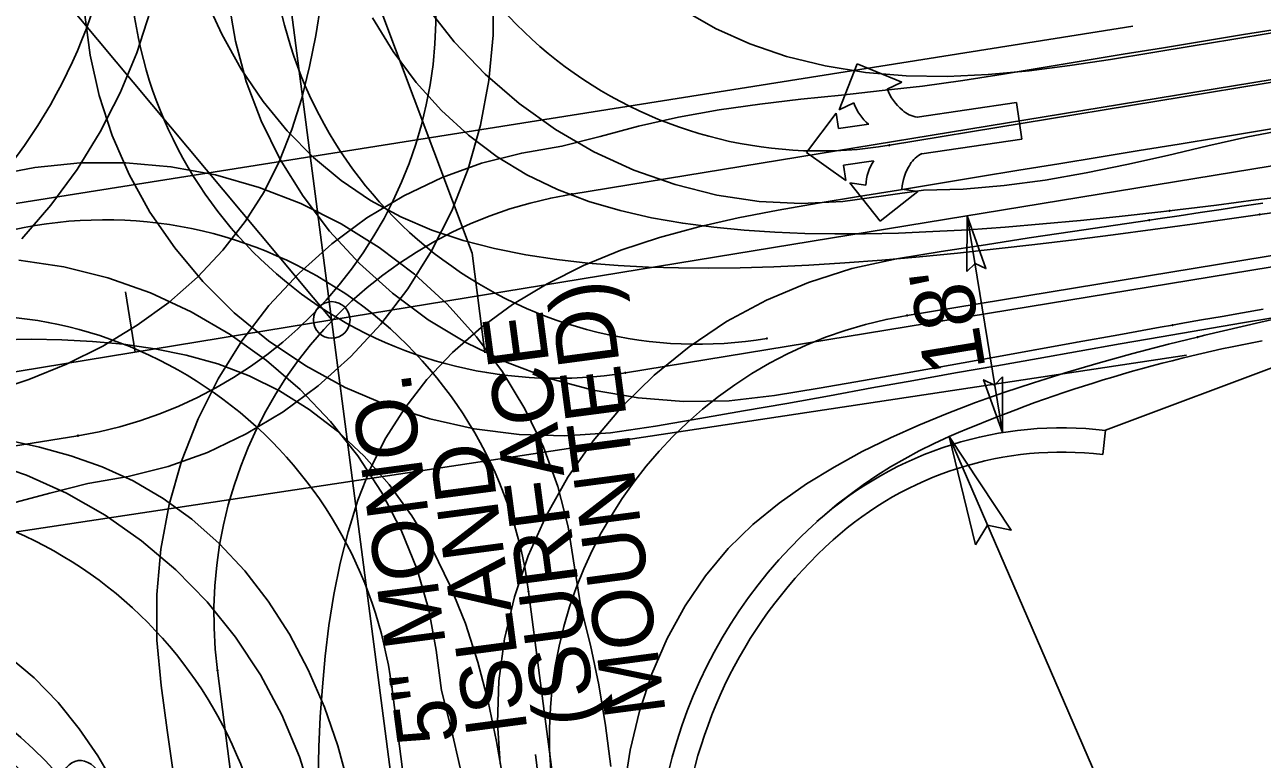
# Model space of a CAD drawing. Extents: x 2367848 to 2369479, y 800728 to 808616.
# Drawn here: x 2368356.4 to 2368457.9, y 807914.7 to 807974.9 of the extents above; entities that cross this region are included whole.
import ezdxf

# ---------------------------------------------------------------- set-up
doc = ezdxf.new("R2010")
doc.units = 0
for name, color, linetype in [('Default', 7, 'Continuous'), ('Prop AutoTurn Projected Path', 7, 'Continuous'), ('Prop AutoTurn Simulation', 7, 'Continuous'), ('Prop Conc 2ft 6in Curb and Gutter', 7, 'Continuous'), ('Prop Dimension', 7, 'Continuous'), ('Prop EOT', 7, 'Continuous'), ('Prop Horizontal Alignment', 7, 'Continuous'), ('Prop Horizontal Alignment Station Label', 7, 'Continuous'), ('Prop Horizontal Alignment Tick Small', 7, 'Continuous'), ('Prop Lane Arrow CELL', 7, 'Continuous'), ('Prop Paved Shoulder', 7, 'Continuous'), ('Prop Terminator CELL', 7, 'Continuous'), ('Prop WCC CELL', 7, 'Continuous'), ('Prop WCR CELL', 7, 'Continuous'), ('Scratch_Level_0', 7, 'Continuous'), ('Scratch_Level_1', 7, 'Continuous')]:
    doc.layers.add(name, color=color, linetype=linetype)

# ---------------------------------------------------------------- blocks, each defined once
blk = doc.blocks.new('CR')
at = {"layer": 'Prop WCC CELL'}
blk.add_ellipse((0.02, -0.02), major_axis=(5.61, 0), ratio=0.462467, dxfattribs=at)
blk.add_text('CR', height=3, dxfattribs=at).set_placement((-2.34, -1.5))

msp = doc.modelspace()

# ---------------------------------------------------------------- linework, layer by layer
at = {"layer": 'Default'}
for p, q in [((2368447.26, 807974.78), (2368313.92, 807953.63)), ((2368318.18, 807927.65), (2368451.68, 807947.82))]:
    msp.add_line(p, q, dxfattribs=at)
at = {"layer": 'Prop AutoTurn Projected Path'}
for p, q in [((2368427.31, 807965.02), (2368461.82, 807970.7)), ((2368428.77, 807951.07), (2368518.53, 807965.84)), ((2368402.03, 807801.48), (2368386.52, 807920.63))]:
    msp.add_line(p, q, dxfattribs=at)
for centre, radius, start, end in [((2368322.12, 807989.26), 42, 279.3467, 7.418), ((2368421.62, 807999.55), 35, 187.418, 279.3467), ((2368421.62, 807999.55), 35, 187.418, 279.3467), ((2368411.59, 807983.71), 35, 187.418, 279.3467), ((2368351.81, 807916.11), 35, 7.418, 99.3467), ((2368434.45, 807916.53), 35, 99.3467, 187.418), ((2368341.65, 807901.26), 35, 7.418, 99.3467)]:
    msp.add_arc(centre, radius, start, end, dxfattribs=at)
at = {"layer": 'Prop AutoTurn Simulation'}
for points in [[(2368373.15, 807976.86), (2368373.7, 807973.55), (2368374.59, 807970.25), (2368375.82, 807967.01), (2368377.38, 807963.86), (2368379.25, 807960.84), (2368381.42, 807957.99), (2368383.87, 807955.33), (2368386.58, 807952.9), (2368389.51, 807950.72), (2368392.66, 807948.81), (2368395.98, 807947.2), (2368399.45, 807945.9), (2368403.03, 807944.93), (2368406.71, 807944.3), (2368410.43, 807944.01), (2368414.17, 807944.08), (2368417.89, 807944.5), (2368421.57, 807945.11), (2368425.19, 807945.74), (2368428.76, 807946.37), (2368432.3, 807947), (2368435.79, 807947.63), (2368439.26, 807948.26), (2368442.7, 807948.88), (2368446.11, 807949.49), (2368449.51, 807950.1), (2368450.53, 807950.28)], [(2368460, 807966.34), (2368456.7, 807965.7), (2368453.41, 807964.96), (2368450.11, 807964.19), (2368446.79, 807963.45), (2368443.45, 807962.76), (2368440.09, 807962.17), (2368436.72, 807961.71), (2368433.37, 807961.41), (2368430.11, 807961.34), (2368426.82, 807960.88), (2368423.49, 807960.4), (2368420.09, 807960.24), (2368416.64, 807960.41), (2368413.18, 807960.93), (2368409.74, 807961.79), (2368406.36, 807962.98), (2368403.09, 807964.49), (2368399.94, 807966.32), (2368396.97, 807968.44), (2368394.19, 807970.85), (2368391.64, 807973.51), (2368389.35, 807976.42)], [(2368366.73, 807975.98), (2368365.63, 807972.61), (2368364.25, 807969.31), (2368362.61, 807966.11), (2368360.72, 807963.04), (2368358.57, 807960.12), (2368356.2, 807957.36)], [(2368384.93, 807975.46), (2368386.63, 807972.7), (2368388.53, 807970.16), (2368390.59, 807967.87), (2368392.81, 807965.84), (2368395.15, 807964.08), (2368397.59, 807962.59), (2368400.1, 807961.38), (2368402.67, 807960.42), (2368405.24, 807959.67), (2368407.81, 807959.08), (2368410.37, 807958.63), (2368412.91, 807958.3), (2368415.42, 807958.05), (2368417.91, 807957.89), (2368420.38, 807957.79), (2368422.83, 807957.75), (2368425.36, 807957.76), (2368428.06, 807957.82), (2368430.88, 807957.94), (2368433.81, 807958.1), (2368436.81, 807958.31), (2368439.88, 807958.57), (2368442.99, 807958.86), (2368446.14, 807959.18), (2368449.32, 807959.54), (2368450.28, 807959.65)], [(2368458.7, 807974.24), (2368455.38, 807973.69), (2368452.06, 807973.15), (2368448.75, 807972.6), (2368445.43, 807972.06), (2368442.1, 807971.55), (2368438.77, 807971.12), (2368435.42, 807970.81), (2368432.06, 807970.67), (2368428.7, 807970.71), (2368425.35, 807970.99), (2368422.06, 807971.52), (2368418.89, 807972.3), (2368415.88, 807973.33), (2368413.05, 807974.6), (2368410.43, 807976.09)], [(2368448.63, 807958.88), (2368449.32, 807958.98), (2368451.06, 807959.24), (2368452.78, 807959.5), (2368454.5, 807959.76), (2368456.21, 807960.02), (2368457.92, 807960.27)], [(2368450.28, 807959.65), (2368450.92, 807959.73), (2368452.53, 807959.92), (2368454.14, 807960.12), (2368455.75, 807960.33), (2368457.36, 807960.54), (2368458.98, 807960.75)], [(2368395.41, 807914.31), (2368395.19, 807917.68), (2368395.31, 807921.11), (2368395.77, 807924.56), (2368396.58, 807927.99), (2368397.71, 807931.36), (2368399.18, 807934.64), (2368400.96, 807937.8), (2368403.03, 807940.79), (2368405.4, 807943.59), (2368408.02, 807946.17), (2368410.89, 807948.5), (2368413.97, 807950.56), (2368417.24, 807952.33), (2368420.67, 807953.78), (2368424.23, 807954.91), (2368427.89, 807955.7), (2368431.56, 807956.3), (2368435.19, 807956.87), (2368438.78, 807957.42), (2368442.33, 807957.95), (2368445.84, 807958.47), (2368448.63, 807958.88)], [(2368392.12, 807913.97), (2368391.4, 807917.2), (2368390.6, 807920.31), (2368390.16, 807923.62), (2368389.55, 807926.94), (2368388.59, 807930.23), (2368387.3, 807933.45), (2368385.67, 807936.57), (2368383.74, 807939.56), (2368381.51, 807942.38), (2368379.01, 807944.99), (2368376.25, 807947.38), (2368373.27, 807949.51), (2368370.09, 807951.36), (2368366.74, 807952.91), (2368363.24, 807954.14), (2368359.64, 807955.05), (2368355.95, 807955.61)], [(2368450.53, 807950.28), (2368451.21, 807950.4), (2368452.89, 807950.7), (2368454.58, 807950.99), (2368456.26, 807951.29), (2368457.95, 807951.58)], [(2368452.58, 807949.29), (2368453.18, 807949.44), (2368454.7, 807949.8), (2368456.23, 807950.16), (2368457.77, 807950.51), (2368459.32, 807950.86)], [(2368405.55, 807912.12), (2368406.06, 807915.42), (2368406.83, 807918.63), (2368407.84, 807921.69), (2368409.09, 807924.57), (2368410.56, 807927.25), (2368412.24, 807929.72), (2368414.1, 807931.95), (2368416.13, 807933.94), (2368418.28, 807935.69), (2368420.51, 807937.25), (2368422.78, 807938.64), (2368425.09, 807939.9), (2368427.41, 807941.04), (2368429.73, 807942.08), (2368432.06, 807943.04), (2368434.38, 807943.92), (2368436.7, 807944.75), (2368439.12, 807945.55), (2368441.71, 807946.36), (2368444.43, 807947.16), (2368447.27, 807947.94), (2368450.19, 807948.7), (2368452.58, 807949.29)], [(2368382.98, 807912.57), (2368382.09, 807915.78), (2368381, 807918.94), (2368379.68, 807922), (2368378.15, 807924.93), (2368376.4, 807927.65), (2368374.47, 807930.14), (2368372.38, 807932.38), (2368370.14, 807934.36), (2368367.77, 807936.06), (2368365.32, 807937.5), (2368362.79, 807938.65), (2368360.22, 807939.57), (2368357.64, 807940.28), (2368355.07, 807940.84)], [(2368353.19, 807939.13), (2368356.58, 807937.97), (2368359.86, 807936.49), (2368363.02, 807934.69), (2368366.01, 807932.6), (2368368.81, 807930.22), (2368371.38, 807927.58), (2368373.71, 807924.7), (2368375.76, 807921.6), (2368377.51, 807918.32), (2368378.96, 807914.88), (2368380.07, 807911.31), (2368380.84, 807907.64), (2368381.35, 807903.94), (2368381.8, 807900.28), (2368382.23, 807896.66), (2368382.65, 807893.09), (2368383.05, 807889.55), (2368383.41, 807886.4)], [(2368355.02, 807923.2), (2368357.22, 807921.35), (2368359.18, 807919.33), (2368360.9, 807917.18), (2368362.42, 807914.95), (2368363.76, 807912.67), (2368364.97, 807910.35), (2368366.06, 807908.03), (2368367.04, 807905.69), (2368367.94, 807903.35), (2368368.77, 807901.02), (2368369.53, 807898.68), (2368370.25, 807896.3), (2368370.97, 807893.75), (2368371.68, 807891.05), (2368372.38, 807888.24), (2368373.05, 807885.33), (2368373.63, 807882.64)]]:
    msp.add_lwpolyline(points, dxfattribs=at)
for centre in [(2368427.31, 807965.02), (2368427.31, 807965.02), (2368448.63, 807958.88), (2368448.63, 807958.88), (2368450.28, 807959.65), (2368450.28, 807959.65), (2368428.77, 807951.07), (2368428.77, 807951.07), (2368450.53, 807950.28), (2368450.53, 807950.28), (2368417.27, 807949.18), (2368417.27, 807949.18), (2368452.58, 807949.29), (2368452.58, 807949.29), (2368386.52, 807920.63), (2368386.52, 807920.63)]:
    msp.add_circle(centre, 0.0417, dxfattribs=at)
at = {"layer": 'Prop Conc 2ft 6in Curb and Gutter'}
msp.add_line((2368444.8, 807939.66), (2368445.04, 807941.65), dxfattribs=at)
for centre, radius, start, end in [((2368441.44, 807911.86), 28, 83.1058, 131.9757), ((2368448.13, 807904.43), 38, 131.9757, 174.5795), ((2368329.43, 807886.68), 38, 20.2566, 51.6871)]:
    msp.add_arc(centre, radius, start, end, dxfattribs=at)
at = {"layer": 'Prop Dimension'}
for p, q in [((2368393.1, 807956.17), (2368377.33, 807998.31)), ((2368433.68, 807959.23), (2368436.59, 807941.47)), ((2368393.1, 807956.17), (2368394.14, 807947.99)), ((2368448.13, 807904.43), (2368432.22, 807941.13)), ((2368479.94, 807831.03), (2368432.22, 807941.13)), ((2368398.3, 807915.08), (2368399.04, 807909.22))]:
    msp.add_line(p, q, dxfattribs=at)
at = {"layer": 'Prop EOT'}
for centre, radius, start, end in [((2368479.94, 807831.03), 120, 100.5964, 113.435), ((2368448.13, 807904.43), 40, 113.435, 174.5795), ((2368329.43, 807886.68), 40, 20.2566, 83.8746)]:
    msp.add_arc(centre, radius, start, end, dxfattribs=at)
at = {"layer": 'Prop Horizontal Alignment'}
for p, q in [((2368427.27, 807599.89), (2368315.24, 808460.34)), ((2368381.6, 807950.7), (2368715.66, 808005.43)), ((2368281.91, 807934.37), (2368381.6, 807950.7))]:
    msp.add_line(p, q, dxfattribs=at)
at = {"layer": 'Prop Horizontal Alignment Station Label'}
msp.add_line((2368381.6, 807950.7), (2368243.01, 808116.67), dxfattribs=at)
msp.add_circle((2368381.6, 807950.7), 1.5, dxfattribs=at)
at = {"layer": 'Prop Horizontal Alignment Tick Small'}
msp.add_line((2368365.5, 807948.06), (2368364.69, 807953), dxfattribs=at)
at = {"layer": 'Prop Lane Arrow CELL'}
for p, q in [((2368423.2, 807967.92), (2368424.67, 807971.69)), ((2368424.67, 807971.69), (2368428.34, 807970.2)), ((2368428.34, 807970.2), (2368427.14, 807969.63)), ((2368424.4, 807968.49), (2368423.2, 807967.92)), ((2368429.59, 807967.33), (2368437.74, 807968.52)), ((2368437.74, 807968.52), (2368438.18, 807965.53)), ((2368420.51, 807964.43), (2368422.94, 807967.64)), ((2368422.94, 807967.64), (2368423.13, 807966.39)), ((2368423.13, 807966.39), (2368425.64, 807966.75)), ((2368438.18, 807965.53), (2368429.98, 807964.33)), ((2368423.75, 807962.14), (2368420.51, 807964.43)), ((2368426.02, 807963.75), (2368423.56, 807963.4)), ((2368423.56, 807963.4), (2368423.75, 807962.14)), ((2368426.55, 807958.81), (2368424.07, 807961.94)), ((2368424.07, 807961.94), (2368425.38, 807961.74)), ((2368429.64, 807961.23), (2368426.55, 807958.81)), ((2368428.33, 807961.43), (2368429.64, 807961.23))]:
    msp.add_line(p, q, dxfattribs=at)
for centre, radius, start, end in [((2368430.9, 807971.01), 4, 199.9243, 230.8545), ((2368428.16, 807969.83), 4, 199.5552, 230.4448), ((2368429.92, 807969.58), 2.28, 227.3644, 262.1304), ((2368430.98, 807962.29), 2.28, 116.2202, 149.2181), ((2368429.37, 807961.55), 4, 146.5345, 177.3109), ((2368432.33, 807961.2), 4, 145.728, 176.9407)]:
    msp.add_arc(centre, radius, start, end, dxfattribs=at)
at = {"layer": 'Prop Paved Shoulder'}
msp.add_line((2368445.04, 807941.65), (2368471.14, 807951.46), dxfattribs=at)
msp.add_arc((2368441.44, 807911.86), 30, 83.1058, 131.9757, dxfattribs=at)
at = {"layer": 'Prop Terminator CELL'}
for points in [[(2368433.67, 807954.67), (2368433.68, 807959.23), (2368435.23, 807954.91), (2368434.34, 807955.34)], [(2368436.59, 807946.04), (2368436.59, 807941.47), (2368435.03, 807945.79), (2368435.92, 807945.36)], [(2368434.38, 807932.26), (2368432.22, 807941.13), (2368437.29, 807933.46), (2368435.36, 807933.88)]]:
    msp.add_lwpolyline(points, close=True, dxfattribs=at)
at = {"layer": 'Scratch_Level_0'}
for p, q in [((2368502.21, 807977.55), (2368401.28, 807961.02)), ((2368413.8, 807805.08), (2368397.74, 807928.43)), ((2368372.23, 807921.96), (2368388.4, 807797.73))]:
    msp.add_line(p, q, dxfattribs=at)
for points in [[(2368459.64, 807974.63), (2368456.35, 807974.09), (2368453.07, 807973.55), (2368449.78, 807973.02), (2368446.49, 807972.48), (2368443.2, 807971.94), (2368439.92, 807971.4), (2368436.63, 807970.86), (2368433.34, 807970.32), (2368430.04, 807969.86), (2368426.72, 807969.5), (2368423.39, 807969.14), (2368420.05, 807968.8), (2368416.7, 807968.4), (2368413.35, 807967.92), (2368410.03, 807967.32), (2368406.76, 807966.59), (2368403.6, 807965.73), (2368400.47, 807964.94), (2368397.17, 807964.38), (2368393.89, 807963.56), (2368390.65, 807962.39), (2368387.5, 807960.88), (2368384.47, 807959.06), (2368381.6, 807956.94), (2368378.92, 807954.54), (2368376.45, 807951.88), (2368374.24, 807948.98), (2368372.29, 807945.87), (2368370.64, 807942.58), (2368369.29, 807939.13), (2368368.27, 807935.56), (2368367.59, 807931.9), (2368367.26, 807928.19), (2368367.27, 807924.45), (2368367.63, 807920.72), (2368368.12, 807917.06), (2368368.63, 807913.44)], [(2368460.93, 807966.74), (2368457.65, 807966.2), (2368454.36, 807965.66), (2368451.07, 807965.12), (2368447.78, 807964.58), (2368444.5, 807964.04), (2368441.21, 807963.51), (2368437.92, 807962.97), (2368434.63, 807962.43), (2368431.35, 807961.89), (2368428.06, 807961.35), (2368424.77, 807960.81), (2368421.48, 807960.27), (2368418.2, 807959.71), (2368414.93, 807959.08), (2368411.68, 807958.34), (2368408.47, 807957.46), (2368405.31, 807956.41), (2368402.23, 807955.15), (2368399.25, 807953.67), (2368396.43, 807951.97), (2368393.84, 807950.09), (2368391.49, 807948.03), (2368389.4, 807945.81), (2368387.58, 807943.47), (2368386.03, 807941.03), (2368384.76, 807938.5), (2368383.75, 807935.93), (2368382.94, 807933.34), (2368382.29, 807930.76), (2368381.77, 807928.2), (2368381.37, 807925.65), (2368381.06, 807923.13), (2368380.83, 807920.63), (2368380.66, 807918.15), (2368380.55, 807915.69), (2368380.49, 807913.11)], [(2368404.47, 807914.1), (2368404.05, 807917.46), (2368403.5, 807920.79), (2368402.82, 807924.04), (2368402.02, 807927.18), (2368401.51, 807930.44), (2368400.99, 807933.74), (2368400.14, 807937.03), (2368398.95, 807940.27), (2368397.42, 807943.42), (2368395.59, 807946.45), (2368393.46, 807949.31), (2368391.05, 807951.99), (2368388.38, 807954.44), (2368385.48, 807956.65), (2368382.37, 807958.59), (2368379.08, 807960.24), (2368375.64, 807961.57), (2368372.07, 807962.59), (2368368.42, 807963.26), (2368364.71, 807963.59), (2368360.98, 807963.58), (2368357.27, 807963.21), (2368353.96, 807962.58)], [(2368395.68, 807912.86), (2368395.12, 807916.15), (2368394.43, 807919.41), (2368393.59, 807922.64), (2368392.56, 807925.81), (2368391.32, 807928.9), (2368389.85, 807931.87), (2368388.17, 807934.65), (2368386.3, 807937.21), (2368384.26, 807939.52), (2368382.07, 807941.57), (2368379.75, 807943.36), (2368377.32, 807944.88), (2368374.82, 807946.12), (2368372.26, 807947.09), (2368369.68, 807947.81), (2368367.1, 807948.33), (2368364.53, 807948.7), (2368361.99, 807948.94), (2368359.47, 807949.07), (2368356.98, 807949.11), (2368354.51, 807949.08)]]:
    msp.add_lwpolyline(points, dxfattribs=at)
for centre in [(2368401.28, 807961.02), (2368401.28, 807961.02), (2368397.74, 807928.43), (2368397.74, 807928.43), (2368372.23, 807921.96), (2368372.23, 807921.96)]:
    msp.add_circle(centre, 0.0417, dxfattribs=at)
for centre, start, end in [((2368406.94, 807926.48), 99.304, 187.418), ((2368363.03, 807923.91), 7.418, 103.9986)]:
    msp.add_arc(centre, 35, start, end, dxfattribs=at)
at = {"layer": 'Scratch_Level_1'}
for p, q in [((2368405.67, 807946.37), (2368526.06, 807966.09)), ((2368282.88, 807928.45), (2368360.8, 807941.21))]:
    msp.add_line(p, q, dxfattribs=at)
for points in [[(2368355.32, 807935.64), (2368358.48, 807936.5), (2368361.61, 807937.29), (2368364.9, 807937.85), (2368368.19, 807938.67), (2368371.43, 807939.84), (2368374.58, 807941.35), (2368377.61, 807943.17), (2368380.48, 807945.29), (2368383.16, 807947.69), (2368385.62, 807950.35), (2368387.84, 807953.25), (2368389.79, 807956.36), (2368391.44, 807959.65), (2368392.79, 807963.1), (2368393.8, 807966.67), (2368394.49, 807970.33), (2368394.82, 807974.04), (2368394.81, 807977.78)], [(2368371.2, 807977.15), (2368372.59, 807974.12), (2368374.18, 807971.26), (2368375.98, 807968.6), (2368377.96, 807966.19), (2368380.11, 807964.02), (2368382.38, 807962.13), (2368384.78, 807960.5), (2368387.26, 807959.15), (2368389.8, 807958.07), (2368392.37, 807957.22), (2368394.95, 807956.56), (2368397.51, 807956.04), (2368400.05, 807955.65), (2368402.58, 807955.36), (2368405.08, 807955.16), (2368407.56, 807955.03), (2368410.02, 807954.96), (2368412.48, 807954.94), (2368415.09, 807954.97), (2368417.85, 807955.06), (2368420.72, 807955.19), (2368423.67, 807955.38), (2368426.7, 807955.61), (2368429.78, 807955.88), (2368432.91, 807956.18), (2368436.06, 807956.52), (2368439.24, 807956.89), (2368442.45, 807957.28), (2368445.67, 807957.69), (2368448.9, 807958.12), (2368452.14, 807958.56), (2368455.39, 807959.02), (2368457.67, 807959.35)], [(2368353.61, 807944.77), (2368356.77, 807945.82), (2368359.85, 807947.08), (2368362.83, 807948.56), (2368365.65, 807950.26), (2368368.24, 807952.14), (2368370.59, 807954.2), (2368372.68, 807956.42), (2368374.5, 807958.76), (2368376.05, 807961.2), (2368377.32, 807963.73), (2368378.33, 807966.3), (2368379.14, 807968.89), (2368379.79, 807971.47), (2368380.3, 807974.03), (2368380.71, 807976.58)], [(2368361.36, 807975.71), (2368361.81, 807972.4), (2368362.53, 807969.09), (2368363.59, 807965.82), (2368364.99, 807962.63), (2368366.7, 807959.54), (2368368.73, 807956.6), (2368371.04, 807953.84), (2368373.61, 807951.29), (2368376.43, 807948.98), (2368379.48, 807946.94), (2368382.71, 807945.17), (2368386.11, 807943.71), (2368389.64, 807942.58), (2368393.27, 807941.77), (2368396.97, 807941.31), (2368400.7, 807941.2), (2368404.44, 807941.44), (2368408.13, 807942), (2368411.77, 807942.61), (2368415.36, 807943.24), (2368418.9, 807943.86), (2368422.4, 807944.49), (2368425.88, 807945.12), (2368429.32, 807945.74), (2368432.74, 807946.35), (2368436.13, 807946.95), (2368439.51, 807947.55), (2368442.88, 807948.14), (2368446.24, 807948.73), (2368449.58, 807949.31), (2368452.92, 807949.88), (2368456.25, 807950.45), (2368458.57, 807950.85)], [(2368457.67, 807959.35), (2368458.65, 807959.49)]]:
    msp.add_lwpolyline(points, dxfattribs=at)
for centre in [(2368457.67, 807959.35), (2368457.67, 807959.35), (2368405.67, 807946.37), (2368405.67, 807946.37), (2368360.8, 807941.21), (2368360.8, 807941.21)]:
    msp.add_circle(centre, 0.0417, dxfattribs=at)
for centre, start, end in [((2368355.14, 807975.75), 279.304, 7.418), ((2368400.02, 807980.91), 187.418, 279.304)]:
    msp.add_arc(centre, 35, start, end, dxfattribs=at)

# ---------------------------------------------------------------- block references
at = {"layer": 'Prop WCR CELL', "rotation": 97.54241161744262}
msp.add_blockref('CR', (2368361.53, 807908.99), dxfattribs=at)

# ---------------------------------------------------------------- texts
at = {"layer": 'Prop Dimension'}
for s, rotation, p in [("18'", 99.304, (2368435.22, 807946.7)), ('MOUNTED)', 97.5241, (2368409, 807918.45)), ('(SURFACE', 97.5241, (2368403.34, 807917.71)), ('5" MONO.', 97.5241, (2368392.01, 807916.21)), ('ISLAND', 97.5241, (2368397.67, 807916.96))]:
    msp.add_text(s, height=5, rotation=rotation, dxfattribs=at).set_placement(p)

doc.saveas('drawing.dxf')
